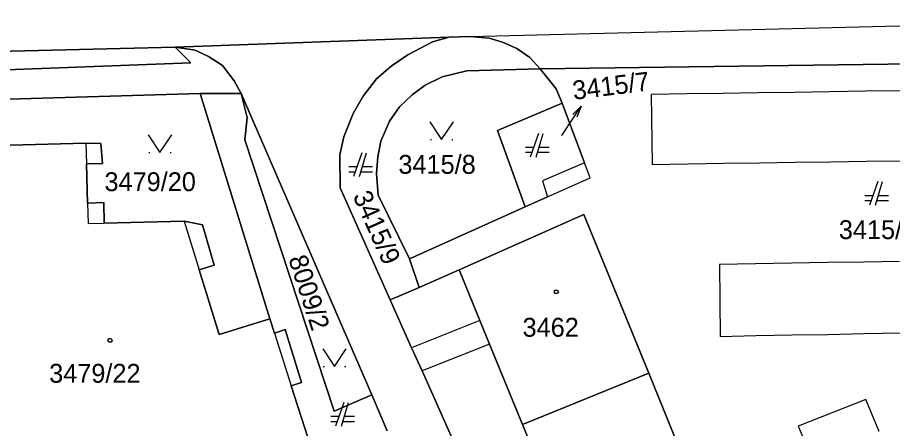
# Model space of a CAD drawing. Extents: x -263587 to -261993, y -1238795 to -1236748.
# Drawn here: x -262845.6 to -262771.6, y -1238395 to -1238360.2 of the extents above; entities that cross this region are included whole.
import ezdxf

# ---------------------------------------------------------------- set-up
doc = ezdxf.new("R2010")
doc.units = 0
doc.layers.add('Vrstva 1', color=7, linetype='Continuous')

msp = doc.modelspace()

# ---------------------------------------------------------------- linework, layer by layer
at = {"layer": 'Vrstva 1'}
for p, q in [((-262807.34, -1238361.81), (-262742.04, -1238360.21)), ((-262832.28, -1238362.71), (-262809.08, -1238361.87)), ((-262809.08, -1238361.87), (-262832.28, -1238362.71)), ((-262809.08, -1238361.87), (-262810.49, -1238362.28)), ((-262810.49, -1238362.28), (-262809.08, -1238361.87)), ((-262809.08, -1238361.87), (-262807.34, -1238361.81)), ((-262807.34, -1238361.81), (-262809.08, -1238361.87)), ((-262807.34, -1238361.81), (-262805.72, -1238361.97)), ((-262805.72, -1238361.97), (-262807.34, -1238361.81)), ((-262805.72, -1238361.97), (-262804.58, -1238362.3)), ((-262804.58, -1238362.3), (-262805.72, -1238361.97)), ((-262885.17, -1238364.02), (-262832.28, -1238362.71)), ((-262832.28, -1238362.71), (-262885.17, -1238364.02)), ((-262830.6, -1238362.98), (-262832.28, -1238362.71)), ((-262832.28, -1238362.71), (-262830.95, -1238364.06)), ((-262830.95, -1238364.06), (-262832.28, -1238362.71)), ((-262832.28, -1238362.71), (-262830.6, -1238362.98)), ((-262810.49, -1238362.28), (-262812.58, -1238363.37)), ((-262812.58, -1238363.37), (-262810.49, -1238362.28)), ((-262804.58, -1238362.3), (-262803.37, -1238362.83)), ((-262803.37, -1238362.83), (-262804.58, -1238362.3)), ((-262829.45, -1238363.51), (-262830.6, -1238362.98)), ((-262830.6, -1238362.98), (-262829.45, -1238363.51)), ((-262828.27, -1238364.29), (-262829.45, -1238363.51)), ((-262829.45, -1238363.51), (-262828.27, -1238364.29)), ((-262812.58, -1238363.37), (-262814.01, -1238364.33)), ((-262814.01, -1238364.33), (-262812.58, -1238363.37)), ((-262803.37, -1238362.83), (-262802.26, -1238363.61)), ((-262802.26, -1238363.61), (-262803.37, -1238362.83)), ((-262830.95, -1238364.06), (-262884.84, -1238366.04)), ((-262884.84, -1238366.04), (-262830.95, -1238364.06)), ((-262802.26, -1238363.61), (-262801.4, -1238364.57)), ((-262801.4, -1238364.57), (-262802.26, -1238363.61)), ((-262801.4, -1238364.57), (-262753.24, -1238363.91)), ((-262753.24, -1238363.91), (-262801.4, -1238364.57)), ((-262827.3, -1238365.58), (-262828.27, -1238364.29)), ((-262828.27, -1238364.29), (-262827.3, -1238365.58)), ((-262814.01, -1238364.33), (-262815.24, -1238365.42)), ((-262815.24, -1238365.42), (-262814.01, -1238364.33)), ((-262807.6, -1238364.74), (-262809.69, -1238365.25)), ((-262809.69, -1238365.25), (-262807.6, -1238364.74)), ((-262801.4, -1238364.57), (-262807.6, -1238364.74)), ((-262807.6, -1238364.74), (-262801.4, -1238364.57)), ((-262801.4, -1238364.57), (-262800.05, -1238366.24)), ((-262800.05, -1238366.24), (-262801.4, -1238364.57)), ((-262826.71, -1238366.64), (-262827.3, -1238365.58)), ((-262827.3, -1238365.58), (-262826.71, -1238366.64)), ((-262815.24, -1238365.42), (-262816.37, -1238366.88)), ((-262816.37, -1238366.88), (-262815.24, -1238365.42)), ((-262809.69, -1238365.25), (-262811.12, -1238365.93)), ((-262811.12, -1238365.93), (-262809.69, -1238365.25)), ((-262811.12, -1238365.93), (-262812.23, -1238366.75)), ((-262812.23, -1238366.75), (-262811.12, -1238365.93)), ((-262800.05, -1238366.24), (-262799.53, -1238367.47)), ((-262799.53, -1238367.47), (-262800.05, -1238366.24)), ((-262773.86, -1238366.46), (-262776.88, -1238366.51)), ((-262770.83, -1238366.42), (-262773.86, -1238366.46)), ((-262830.17, -1238366.65), (-262850.63, -1238367.27)), ((-262850.63, -1238367.27), (-262830.17, -1238366.65)), ((-262830.17, -1238366.65), (-262826.71, -1238366.64)), ((-262826.71, -1238366.64), (-262830.17, -1238366.65)), ((-262824.27, -1238385.74), (-262830.17, -1238366.65)), ((-262830.17, -1238366.65), (-262824.27, -1238385.74)), ((-262815.64, -1238392.16), (-262826.71, -1238366.64)), ((-262826.19, -1238368.67), (-262826.71, -1238366.64)), ((-262826.71, -1238366.64), (-262815.64, -1238392.16)), ((-262826.71, -1238366.64), (-262826.19, -1238368.67)), ((-262816.37, -1238366.88), (-262817.22, -1238368.33)), ((-262817.22, -1238368.33), (-262816.37, -1238366.88)), ((-262812.23, -1238366.75), (-262813.31, -1238367.79)), ((-262813.31, -1238367.79), (-262812.23, -1238366.75)), ((-262788.97, -1238366.68), (-262792, -1238366.73)), ((-262792, -1238366.73), (-262791.91, -1238372.65)), ((-262785.95, -1238366.64), (-262788.97, -1238366.68)), ((-262782.93, -1238366.6), (-262785.95, -1238366.64)), ((-262779.9, -1238366.55), (-262782.93, -1238366.6)), ((-262776.88, -1238366.51), (-262779.9, -1238366.55)), ((-262813.31, -1238367.79), (-262814.13, -1238369)), ((-262814.13, -1238369), (-262813.31, -1238367.79)), ((-262799.53, -1238367.47), (-262805, -1238369.79)), ((-262805, -1238369.79), (-262799.53, -1238367.47)), ((-262799.53, -1238367.47), (-262797.65, -1238372.51)), ((-262797.65, -1238372.51), (-262799.53, -1238367.47)), ((-262798.634, -1238368.436), (-262797.92, -1238367.708)), ((-262826.38, -1238370.57), (-262826.19, -1238368.67)), ((-262826.19, -1238368.67), (-262826.38, -1238370.57)), ((-262817.22, -1238368.33), (-262818, -1238370.32)), ((-262818, -1238370.32), (-262817.22, -1238368.33)), ((-262814.13, -1238369), (-262814.89, -1238370.7)), ((-262814.89, -1238370.7), (-262814.13, -1238369)), ((-262805, -1238369.79), (-262802.67, -1238376.26)), ((-262802.67, -1238376.26), (-262805, -1238369.79)), ((-262801.54, -1238370.03), (-262802.24, -1238372.03)), ((-262801.74, -1238372.03), (-262801.14, -1238370.03)), ((-262850.52, -1238371.14), (-262839.85, -1238370.85)), ((-262839.85, -1238370.85), (-262850.52, -1238371.14)), ((-262839.85, -1238370.85), (-262838.57, -1238370.88)), ((-262838.57, -1238370.88), (-262839.85, -1238370.85)), ((-262839.85, -1238370.85), (-262839.8, -1238372.61)), ((-262838.57, -1238370.88), (-262838.43, -1238372.57)), ((-262838.43, -1238372.57), (-262838.57, -1238370.88)), ((-262818.82, -1238393.56), (-262826.38, -1238370.57)), ((-262826.38, -1238370.57), (-262818.82, -1238393.56)), ((-262818, -1238370.32), (-262818.35, -1238371.85)), ((-262818.35, -1238371.85), (-262818, -1238370.32)), ((-262814.89, -1238370.7), (-262815.13, -1238372.01)), ((-262815.13, -1238372.01), (-262814.89, -1238370.7)), ((-262810.68, -1238370.55), (-262810.58, -1238370.55)), ((-262808.88, -1238370.55), (-262808.78, -1238370.55)), ((-262834.52, -1238371.65), (-262834.42, -1238371.65)), ((-262832.72, -1238371.65), (-262832.62, -1238371.65)), ((-262816.48, -1238371.67), (-262817.18, -1238373.67)), ((-262816.68, -1238373.67), (-262816.08, -1238371.67)), ((-262801.96, -1238371.23), (-262802.64, -1238371.23)), ((-262802.64, -1238371.63), (-262802.1, -1238371.63)), ((-262801.62, -1238371.63), (-262800.64, -1238371.63)), ((-262800.64, -1238371.23), (-262801.5, -1238371.23)), ((-262818.35, -1238371.85), (-262818.32, -1238374.64)), ((-262818.32, -1238374.64), (-262818.35, -1238371.85)), ((-262815.13, -1238372.01), (-262815.25, -1238373.43)), ((-262815.25, -1238373.43), (-262815.13, -1238372.01)), ((-262779.81, -1238372.47), (-262776.79, -1238372.43)), ((-262776.79, -1238372.43), (-262773.77, -1238372.38)), ((-262773.77, -1238372.38), (-262770.74, -1238372.34)), ((-262838.43, -1238372.57), (-262839.8, -1238372.61)), ((-262839.8, -1238372.61), (-262838.43, -1238372.57)), ((-262839.8, -1238372.61), (-262839.7, -1238375.93)), ((-262839.7, -1238375.93), (-262839.8, -1238372.61)), ((-262816.9, -1238372.87), (-262817.58, -1238372.87)), ((-262815.58, -1238372.87), (-262816.44, -1238372.87)), ((-262797.65, -1238372.51), (-262801.19, -1238374.05)), ((-262797.17, -1238373.8), (-262797.65, -1238372.51)), ((-262791.91, -1238372.65), (-262788.89, -1238372.6)), ((-262788.89, -1238372.6), (-262785.86, -1238372.56)), ((-262785.86, -1238372.56), (-262782.84, -1238372.51)), ((-262782.84, -1238372.51), (-262779.81, -1238372.47)), ((-262817.58, -1238373.27), (-262817.04, -1238373.27)), ((-262816.56, -1238373.27), (-262815.58, -1238373.27)), ((-262815.25, -1238373.43), (-262815.11, -1238375.27)), ((-262815.11, -1238375.27), (-262815.25, -1238373.43)), ((-262800.78, -1238375.41), (-262797.17, -1238373.8)), ((-262818.32, -1238374.64), (-262814.1, -1238384.12)), ((-262814.1, -1238384.12), (-262818.32, -1238374.64)), ((-262801.19, -1238374.05), (-262800.78, -1238375.41)), ((-262772.82, -1238374.11), (-262773.52, -1238376.11)), ((-262773.02, -1238376.11), (-262772.42, -1238374.11)), ((-262815.11, -1238375.27), (-262812.46, -1238380.65)), ((-262812.46, -1238380.65), (-262815.11, -1238375.27)), ((-262773.24, -1238375.31), (-262773.92, -1238375.31)), ((-262771.92, -1238375.31), (-262772.78, -1238375.31)), ((-262839.7, -1238375.93), (-262838.32, -1238375.89)), ((-262838.32, -1238375.89), (-262839.7, -1238375.93)), ((-262839.7, -1238375.93), (-262839.66, -1238377.66)), ((-262838.32, -1238375.89), (-262838.28, -1238377.63)), ((-262838.28, -1238377.63), (-262838.32, -1238375.89)), ((-262800.78, -1238375.41), (-262802.67, -1238376.26)), ((-262802.67, -1238376.26), (-262800.78, -1238375.41)), ((-262773.92, -1238375.71), (-262773.38, -1238375.71)), ((-262772.9, -1238375.71), (-262771.92, -1238375.71)), ((-262802.67, -1238376.26), (-262812.46, -1238380.65)), ((-262812.46, -1238380.65), (-262802.67, -1238376.26)), ((-262838.28, -1238377.63), (-262831.52, -1238377.46)), ((-262831.52, -1238377.46), (-262838.28, -1238377.63)), ((-262831.52, -1238377.46), (-262829.97, -1238377.78)), ((-262829.97, -1238377.78), (-262831.52, -1238377.46)), ((-262831.52, -1238377.46), (-262830.26, -1238381.58)), ((-262808.25, -1238381.59), (-262797.69, -1238376.89)), ((-262797.69, -1238376.89), (-262808.25, -1238381.59)), ((-262797.69, -1238376.89), (-262792.2, -1238390.33)), ((-262792.2, -1238390.33), (-262797.69, -1238376.89)), ((-262839.66, -1238377.66), (-262838.28, -1238377.63)), ((-262829.97, -1238377.78), (-262828.97, -1238381.18)), ((-262828.97, -1238381.18), (-262829.97, -1238377.78)), ((-262828.97, -1238381.18), (-262830.26, -1238381.58)), ((-262830.26, -1238381.58), (-262828.97, -1238381.18)), ((-262812.46, -1238380.65), (-262811.62, -1238383.07)), ((-262811.62, -1238383.07), (-262812.46, -1238380.65)), ((-262783.17, -1238381.07), (-262786.21, -1238381.12)), ((-262786.21, -1238381.12), (-262786.16, -1238387.22)), ((-262780.13, -1238381.02), (-262783.17, -1238381.07)), ((-262777.08, -1238380.97), (-262780.13, -1238381.02)), ((-262774.03, -1238380.93), (-262777.08, -1238380.97)), ((-262770.97, -1238380.88), (-262774.03, -1238380.93)), ((-262830.26, -1238381.58), (-262828.57, -1238387.06)), ((-262828.57, -1238387.06), (-262830.26, -1238381.58)), ((-262811.62, -1238383.07), (-262808.25, -1238381.59)), ((-262808.25, -1238381.59), (-262811.62, -1238383.07)), ((-262808.25, -1238381.59), (-262806.49, -1238385.87)), ((-262806.49, -1238385.87), (-262808.25, -1238381.59)), ((-262814.1, -1238384.12), (-262811.62, -1238383.07)), ((-262811.62, -1238383.07), (-262814.1, -1238384.12)), ((-262814.1, -1238384.12), (-262812.28, -1238388.18)), ((-262812.28, -1238388.18), (-262814.1, -1238384.12)), ((-262828.57, -1238387.06), (-262824.27, -1238385.74)), ((-262824.27, -1238385.74), (-262828.57, -1238387.06)), ((-262823.88, -1238386.94), (-262824.27, -1238385.74)), ((-262824.27, -1238385.74), (-262823.88, -1238386.94)), ((-262806.49, -1238385.87), (-262812.28, -1238388.18)), ((-262806.49, -1238385.87), (-262805.67, -1238387.87)), ((-262805.67, -1238387.87), (-262806.49, -1238385.87)), ((-262822.98, -1238386.65), (-262823.88, -1238386.94)), ((-262823.88, -1238386.94), (-262822.98, -1238386.65)), ((-262823.88, -1238386.94), (-262822.46, -1238391.4)), ((-262821.6, -1238391.12), (-262822.98, -1238386.65)), ((-262822.98, -1238386.65), (-262821.6, -1238391.12)), ((-262786.16, -1238387.22), (-262783.12, -1238387.16)), ((-262783.12, -1238387.16), (-262780.08, -1238387.1)), ((-262780.08, -1238387.1), (-262777.04, -1238387.05)), ((-262777.04, -1238387.05), (-262773.98, -1238386.99)), ((-262773.98, -1238386.99), (-262770.93, -1238386.93)), ((-262805.67, -1238387.87), (-262811.39, -1238390.15)), ((-262805.67, -1238387.87), (-262802.88, -1238394.68)), ((-262802.88, -1238394.68), (-262805.67, -1238387.87)), ((-262812.28, -1238388.18), (-262811.39, -1238390.15)), ((-262811.39, -1238390.15), (-262812.28, -1238388.18)), ((-262819.75, -1238389.78), (-262819.65, -1238389.78)), ((-262817.95, -1238389.78), (-262817.85, -1238389.78)), ((-262811.39, -1238390.15), (-262807.41, -1238399.06)), ((-262807.41, -1238399.06), (-262811.39, -1238390.15)), ((-262802.88, -1238394.68), (-262792.2, -1238390.33)), ((-262792.2, -1238390.33), (-262802.88, -1238394.68)), ((-262792.2, -1238390.33), (-262785.23, -1238407.4)), ((-262785.23, -1238407.4), (-262792.2, -1238390.33)), ((-262822.46, -1238391.4), (-262821.6, -1238391.12)), ((-262821.6, -1238391.12), (-262822.46, -1238391.4)), ((-262820.13, -1238398.69), (-262822.46, -1238391.4)), ((-262822.46, -1238391.4), (-262820.13, -1238398.69)), ((-262815.64, -1238392.16), (-262818.82, -1238393.56)), ((-262818.82, -1238393.56), (-262815.64, -1238392.16)), ((-262814.33, -1238395.23), (-262815.64, -1238392.16)), ((-262815.64, -1238392.16), (-262814.33, -1238395.23)), ((-262818.01, -1238392.82), (-262818.71, -1238394.82)), ((-262818.21, -1238394.82), (-262817.61, -1238392.82)), ((-262773.84, -1238392.57), (-262779.55, -1238394.82)), ((-262772.71, -1238395.27), (-262773.84, -1238392.57)), ((-262818.43, -1238394.02), (-262819.11, -1238394.02)), ((-262819.11, -1238394.42), (-262818.57, -1238394.42)), ((-262818.09, -1238394.42), (-262817.11, -1238394.42)), ((-262817.11, -1238394.02), (-262817.97, -1238394.02)), ((-262802.88, -1238394.68), (-262799.74, -1238402.35)), ((-262799.74, -1238402.35), (-262802.88, -1238394.68)), ((-262779.55, -1238394.82), (-262778.42, -1238397.51))]:
    msp.add_line(p, q, dxfattribs=at)
for points in [[(-262799.56, -1238370.22), (-262797.92, -1238367.708), (-262798.299, -1238368.654)], [(-262810.73, -1238369.05), (-262809.73, -1238370.55), (-262808.73, -1238369.05)], [(-262834.57, -1238370.15), (-262833.57, -1238371.65), (-262832.57, -1238370.15)], [(-262819.8, -1238388.28), (-262818.8, -1238389.78), (-262817.8, -1238388.28)]]:
    msp.add_lwpolyline(points, dxfattribs=at)
for points in [[(-262799.94, -1238383.3), (-262799.85, -1238383.45), (-262799.94, -1238383.6), (-262800.12, -1238383.6), (-262800.21, -1238383.45), (-262800.12, -1238383.3)], [(-262837.7, -1238387.41), (-262837.61, -1238387.56), (-262837.7, -1238387.71), (-262837.88, -1238387.71), (-262837.97, -1238387.56), (-262837.88, -1238387.41)]]:
    msp.add_lwpolyline(points, close=True, dxfattribs=at)

# ---------------------------------------------------------------- texts
for s, rotation, p in [('3415/7', 7.10468, (-262798.554, -1238367.19)), ('3415/9', 294.04194, (-262817.275, -1238375.324)), ('8009/2', 288.02588, (-262822.719, -1238380.636))]:
    msp.add_text(s, height=1.6, rotation=rotation, dxfattribs=at).set_placement(p)
for s, p in [('3415/8', (-262813.39, -1238373.45)), ('3479/20', (-262838.267, -1238374.92)), ('3415/1', (-262776.111, -1238378.98)), ('3462', (-262802.882, -1238387.25)), ('3479/22', (-262842.947, -1238391.15))]:
    msp.add_text(s, height=1.6, dxfattribs=at).set_placement(p)

doc.saveas('drawing.dxf')
